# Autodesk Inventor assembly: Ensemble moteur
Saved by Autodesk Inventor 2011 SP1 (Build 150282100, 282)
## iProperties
Created: 2010-12
Part Number: Ensemble moteur
Document SubType Name: Assembly
Designer: eric
Author: eric
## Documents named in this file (8)
- D:\eduinventor\maquettesaip2011\machineàpain\Workspace\Ensemble moteur.iam
- D:\eduinventor\maquettesaip2011\machineàpain\Workspace\flasque moteur.ipt
- D:\eduinventor\maquettesaip2011\machineàpain\Workspace\flasque moteur_flasque arrière.ipt
- D:\eduinventor\maquettesaip2011\machineàpain\Workspace\stator.ipt
- D:\eduinventor\maquettesaip2011\machineàpain\Workspace\silent-bloc.ipt
- D:\eduinventor\maquettesaip2011\machineàpain\Workspace\Rondelle, W 4.ipt
- D:\eduinventor\maquettesaip2011\machineàpain\Workspace\vis M4x36.ipt
- D:\eduinventor\maquettesaip2011\machineàpain\Workspace\Ecrou hexagonal ISO 4032, M 4.ipt
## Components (18 placed, 6 different names)
1. flasque moteur:1
2. flasque moteur:2
3. stator:1
4. silent-bloc:1
5. silent-bloc:2
6. silent-bloc:3
7. Rondelle, W 4:1
8. vis M4x36:1
9. Ecrou hexagonal ISO 4032, M 4:1
10. Ecrou hexagonal ISO 4032, M 4:4
11. Ecrou hexagonal ISO 4032, M 4:5
12. vis M4x36:4
13. vis M4x36:5
14. Rondelle, W 4:4
15. Rondelle, W 4:5
16. Rondelle, W 4:6
17. vis M4x36:6
18. Ecrou hexagonal ISO 4032, M 4:6
